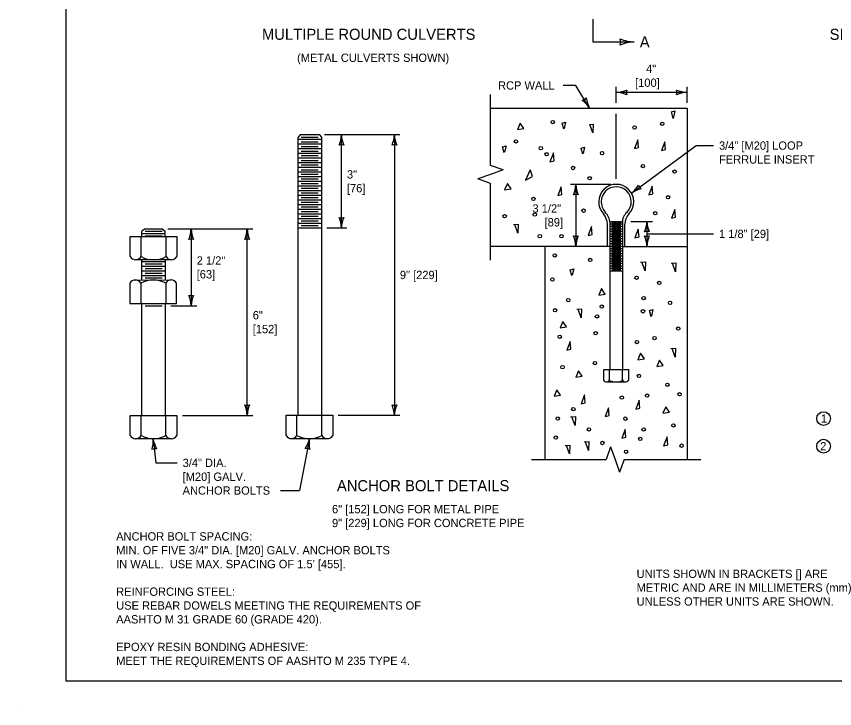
# Model space of a CAD drawing. Extents: x 49988.5 to 50021, y 49987.6 to 50011.4.
# Drawn here: x 49999.98 to 50005.9, y 49999.86 to 50004.87 of the extents above; entities that cross this region are included whole.
import ezdxf

# ---------------------------------------------------------------- set-up
doc = ezdxf.new("R2010")
doc.units = 0
for name, color, linetype in [('Level 1', 7, 'Continuous'), ('Level 2', 7, 'Continuous'), ('Level 3', 7, 'Continuous'), ('Level 5', 7, 'Continuous'), ('Level 6', 7, 'Continuous')]:
    doc.layers.add(name, color=color, linetype=linetype)

msp = doc.modelspace()

# ---------------------------------------------------------------- linework, layer by layer
at = {"layer": 'Level 1'}
for p, q in [((50003.4095, 50004.2058), (50004.8319, 50004.2058)), ((50004.8319, 50004.2058), (50004.8319, 50001.6643)), ((50002.0324, 50004.0145), (50002.0154, 50003.9975)), ((50002.0154, 50001.9847), (50002.0154, 50003.9975)), ((50002.0154, 50003.9808), (50002.1843, 50003.9808)), ((50002.0324, 50004.0145), (50002.1673, 50004.0145)), ((50002.0379, 50003.9976), (50002.1618, 50003.9976)), ((50002.0379, 50003.9638), (50002.1618, 50003.9638)), ((50002.1673, 50004.0145), (50002.1843, 50003.9975)), ((50002.1843, 50003.9975), (50002.1843, 50001.9847)), ((50002.0154, 50003.947), (50002.1843, 50003.947)), ((50002.0154, 50003.9133), (50002.1843, 50003.9133)), ((50002.0379, 50003.9301), (50002.1618, 50003.9301)), ((50002.0379, 50003.8963), (50002.1618, 50003.8963)), ((50002.0154, 50003.8795), (50002.1843, 50003.8795)), ((50002.0154, 50003.8458), (50002.1843, 50003.8458)), ((50002.0379, 50003.8626), (50002.1618, 50003.8626)), ((50002.0154, 50003.812), (50002.1843, 50003.812)), ((50002.0154, 50003.7783), (50002.1843, 50003.7783)), ((50002.0379, 50003.8288), (50002.1618, 50003.8288)), ((50002.0379, 50003.7951), (50002.1618, 50003.7951)), ((50002.0154, 50003.7445), (50002.1843, 50003.7445)), ((50002.0379, 50003.7613), (50002.1618, 50003.7613)), ((50002.0379, 50003.7276), (50002.1618, 50003.7276)), ((50002.0154, 50003.7108), (50002.1843, 50003.7108)), ((50002.0154, 50003.677), (50002.1843, 50003.677)), ((50002.0379, 50003.6938), (50002.1618, 50003.6938)), ((50002.0379, 50003.6601), (50002.1618, 50003.6601)), ((50002.0154, 50003.6433), (50002.1843, 50003.6433)), ((50002.0154, 50003.6095), (50002.1843, 50003.6095)), ((50002.0379, 50003.6263), (50002.1618, 50003.6263)), ((50002.0154, 50003.5758), (50002.1843, 50003.5758)), ((50002.0154, 50003.542), (50002.1843, 50003.542)), ((50002.0379, 50003.5926), (50002.1618, 50003.5926)), ((50002.0379, 50003.5588), (50002.1618, 50003.5588)), ((50002.0154, 50003.5083), (50002.1843, 50003.5083)), ((50002.0379, 50003.5251), (50002.1618, 50003.5251)), ((50002.0379, 50003.4913), (50002.1618, 50003.4913)), ((50002.0154, 50003.4745), (50002.1843, 50003.4745)), ((50002.0154, 50003.4408), (50002.1843, 50003.4408)), ((50002.0379, 50003.4576), (50002.1618, 50003.4576)), ((50002.0379, 50003.4238), (50002.1618, 50003.4238)), ((50002.0154, 50003.407), (50002.1843, 50003.407)), ((50002.0154, 50003.3733), (50002.1843, 50003.3733)), ((50002.0379, 50003.3901), (50002.1618, 50003.3901)), ((50004.2563, 50003.2059), (50004.2563, 50003.3676)), ((50004.2829, 50003.3871), (50004.2739, 50003.3781)), ((50004.2739, 50002.3146), (50004.2739, 50003.3781)), ((50004.2739, 50003.3693), (50004.3631, 50003.3693)), ((50004.2829, 50003.3871), (50004.3541, 50003.3871)), ((50004.2858, 50003.3781), (50004.3512, 50003.3781)), ((50004.3541, 50003.3871), (50004.3631, 50003.3781)), ((50004.3631, 50003.3781), (50004.3631, 50002.3146)), ((50004.3807, 50003.2059), (50004.3807, 50003.3676)), ((50000.9083, 50003.3327), (50000.8858, 50003.3159)), ((50000.8858, 50003.2782), (50000.8858, 50003.3159)), ((50000.9083, 50003.3327), (50001.032, 50003.3327)), ((50000.9083, 50003.3159), (50001.032, 50003.3159)), ((50001.032, 50003.3327), (50001.0545, 50003.3159)), ((50001.0545, 50003.2782), (50001.0545, 50003.3159)), ((50002.0154, 50003.3395), (50002.1843, 50003.3395)), ((50002.0379, 50003.3563), (50002.1618, 50003.3563)), ((50004.2739, 50003.3514), (50004.3631, 50003.3514)), ((50004.2739, 50003.3336), (50004.3631, 50003.3336)), ((50004.2739, 50003.3157), (50004.3631, 50003.3157)), ((50004.2858, 50003.3602), (50004.3512, 50003.3602)), ((50004.2858, 50003.3425), (50004.3512, 50003.3425)), ((50004.2858, 50003.3246), (50004.3512, 50003.3246)), ((50004.2858, 50003.3068), (50004.3512, 50003.3068)), ((50000.8012, 50003.132), (50000.8012, 50003.2782)), ((50000.8012, 50003.2782), (50001.1387, 50003.2782)), ((50000.8799, 50003.132), (50000.8799, 50003.2782)), ((50000.8858, 50003.2989), (50001.0545, 50003.2989)), ((50000.9083, 50003.2821), (50001.032, 50003.2821)), ((50001.0599, 50003.132), (50001.0599, 50003.2782)), ((50001.1387, 50003.2782), (50001.1387, 50003.132)), ((50004.2739, 50003.2979), (50004.3631, 50003.2979)), ((50004.2739, 50003.2801), (50004.3631, 50003.2801)), ((50004.2739, 50003.2623), (50004.3631, 50003.2623)), ((50004.2858, 50003.289), (50004.3512, 50003.289)), ((50004.2858, 50003.2712), (50004.3512, 50003.2712)), ((50004.2858, 50003.2533), (50004.3512, 50003.2533)), ((50004.2739, 50003.2058), (50003.4095, 50003.2058)), ((50003.8052, 50001.6643), (50003.8052, 50003.2058)), ((50004.2739, 50003.2445), (50004.3631, 50003.2445)), ((50004.2739, 50003.2267), (50004.3631, 50003.2267)), ((50004.2739, 50003.2088), (50004.3631, 50003.2088)), ((50004.2739, 50003.191), (50004.3631, 50003.191)), ((50004.2858, 50003.2355), (50004.3512, 50003.2355)), ((50004.2858, 50003.2176), (50004.3512, 50003.2176)), ((50004.2858, 50003.1999), (50004.3512, 50003.1999)), ((50004.3631, 50003.2058), (50004.8319, 50003.2058)), ((50004.2739, 50003.1731), (50004.3631, 50003.1731)), ((50004.2739, 50003.1553), (50004.3631, 50003.1553)), ((50004.2739, 50003.1375), (50004.3631, 50003.1375)), ((50004.2858, 50003.182), (50004.3512, 50003.182)), ((50004.2858, 50003.1642), (50004.3512, 50003.1642)), ((50004.2858, 50003.1464), (50004.3512, 50003.1464)), ((50004.2858, 50003.1286), (50004.3512, 50003.1286)), ((50001.0993, 50003.1092), (50000.8405, 50003.1095)), ((50000.8858, 50002.9632), (50000.8858, 50003.1095)), ((50000.8858, 50003.0964), (50001.0545, 50003.0964)), ((50000.9083, 50003.0796), (50001.032, 50003.0796)), ((50001.0545, 50003.1092), (50001.0545, 50002.9635)), ((50004.2739, 50003.1197), (50004.3631, 50003.1197)), ((50004.2739, 50003.1019), (50004.3631, 50003.1019)), ((50004.2739, 50003.0841), (50004.3631, 50003.0841)), ((50004.2858, 50003.1107), (50004.3512, 50003.1107)), ((50004.2858, 50003.0929), (50004.3512, 50003.0929)), ((50004.2858, 50003.075), (50004.3512, 50003.075)), ((50000.8858, 50003.0627), (50001.0545, 50003.0627)), ((50000.8858, 50003.0289), (50001.0545, 50003.0289)), ((50000.9083, 50003.0459), (50001.032, 50003.0459)), ((50000.9083, 50003.0121), (50001.032, 50003.0121)), ((50004.2739, 50003.0662), (50004.3631, 50003.0662)), ((50004.2739, 50003.0484), (50004.3631, 50003.0484)), ((50004.2739, 50003.0305), (50004.3631, 50003.0305)), ((50004.2858, 50003.0573), (50004.3512, 50003.0573)), ((50004.2858, 50003.0394), (50004.3512, 50003.0394)), ((50000.838, 50002.9631), (50001.0969, 50002.9635)), ((50000.8858, 50002.9952), (50001.0545, 50002.9952)), ((50000.9083, 50002.9784), (50001.032, 50002.9784)), ((50000.7986, 50002.9406), (50000.7986, 50002.7943)), ((50000.8774, 50002.9406), (50000.8774, 50002.7943)), ((50001.0575, 50002.9406), (50001.0575, 50002.7943)), ((50001.1363, 50002.7943), (50001.1363, 50002.9406)), ((50000.7986, 50002.7943), (50001.1363, 50002.7943)), ((50000.8858, 50001.984), (50000.8858, 50002.7943)), ((50000.8858, 50002.7927), (50001.0545, 50002.7927)), ((50000.9083, 50002.7759), (50001.032, 50002.7759)), ((50001.0545, 50002.7943), (50001.0545, 50001.984)), ((50004.2281, 50002.2373), (50004.2281, 50002.3146)), ((50004.2281, 50002.3146), (50004.4064, 50002.3146)), ((50004.2698, 50002.2373), (50004.2698, 50002.3146)), ((50004.3648, 50002.2373), (50004.3648, 50002.3146)), ((50004.4064, 50002.3146), (50004.4064, 50002.2373)), ((50004.249, 50002.2255), (50004.3856, 50002.2253)), ((50000.8004, 50001.8377), (50000.8004, 50001.984)), ((50000.8004, 50001.984), (50001.1381, 50001.984)), ((50000.8792, 50001.8377), (50000.8792, 50001.984)), ((50001.0593, 50001.8377), (50001.0593, 50001.984)), ((50001.1381, 50001.984), (50001.1381, 50001.8377)), ((50001.9286, 50001.8384), (50001.9286, 50001.9847)), ((50001.9286, 50001.9847), (50002.2663, 50001.9847)), ((50002.0074, 50001.8384), (50002.0074, 50001.9847)), ((50002.1875, 50001.8384), (50002.1875, 50001.9847)), ((50002.2663, 50001.9847), (50002.2663, 50001.8384)), ((50001.0987, 50001.8148), (50000.8398, 50001.8152)), ((50001.968, 50001.8159), (50002.2269, 50001.8155)), ((49999.9766, 49999.8624), (49999.9766, 49999.8624))]:
    msp.add_line(p, q, dxfattribs=at)
msp.add_lwpolyline([(50008.6146, 50011.2628), (50000.3356, 50011.2628), (50000.3356, 50000.0624), (50008.6146, 50000.0624)], close=True, dxfattribs=at)
for points in [[(50004.7314, 50004.1318), (50004.7183, 50004.1789), (50004.7428, 50004.1862), (50004.7314, 50004.1319)], [(50003.6238, 50004.0981), (50003.6042, 50004.0515), (50003.6507, 50004.0589), (50003.6238, 50004.0981)], [(50003.9397, 50004.054), (50003.9274, 50004.0981), (50003.9519, 50004.1054), (50003.9421, 50004.0589)], [(50004.1274, 50004.089), (50004.1526, 50004.0908), (50004.1502, 50004.0271), (50004.1278, 50004.089)], [(50004.4759, 50003.9781), (50004.4514, 50003.9144), (50004.4808, 50003.9218), (50004.4759, 50003.9781)], [(50004.6717, 50003.9634), (50004.6472, 50003.8997), (50004.6766, 50003.9071), (50004.6717, 50003.9634)], [(50003.5087, 50003.8826), (50003.4964, 50003.9267), (50003.5209, 50003.934), (50003.5111, 50003.8875)], [(50004.0768, 50003.8728), (50004.0645, 50003.9169), (50004.089, 50003.9242), (50004.0792, 50003.8777)], [(50003.8636, 50003.8826), (50003.8391, 50003.8189), (50003.8685, 50003.8263), (50003.8636, 50003.8826)], [(50003.6948, 50003.7602), (50003.663, 50003.6843), (50003.7119, 50003.7112), (50003.6972, 50003.7553)], [(50003.5308, 50003.6623), (50003.5112, 50003.6157), (50003.5577, 50003.6231), (50003.5308, 50003.6623)], [(50003.9204, 50003.6383), (50003.8959, 50003.5746), (50003.9253, 50003.582), (50003.9204, 50003.6383)], [(50004.5784, 50003.6423), (50004.5539, 50003.5786), (50004.5833, 50003.586), (50004.5784, 50003.6423)], [(50004.7434, 50003.4735), (50004.7189, 50003.4098), (50004.7483, 50003.4172), (50004.7434, 50003.4735)], [(50003.5747, 50003.3635), (50003.609, 50003.366), (50003.6066, 50003.3023), (50003.5845, 50003.3635)], [(50004.1394, 50003.3495), (50004.1149, 50003.2858), (50004.1443, 50003.2932), (50004.1394, 50003.3495)], [(50004.4787, 50003.3318), (50004.4542, 50003.2681), (50004.4836, 50003.2755), (50004.4787, 50003.3318)], [(50004.4954, 50003.0917), (50004.5297, 50003.0942), (50004.5273, 50003.0305), (50004.5052, 50003.0917)], [(50004.7158, 50003.0843), (50004.7501, 50003.0868), (50004.7477, 50003.0231), (50004.7256, 50003.0843)], [(50003.9985, 50002.9937), (50003.9862, 50003.0378), (50004.0107, 50003.0451), (50004.0009, 50002.9986)], [(50004.2115, 50002.9008), (50004.1919, 50002.8542), (50004.2384, 50002.8616), (50004.2115, 50002.9008)], [(50004.0326, 50002.7513), (50004.0669, 50002.7538), (50004.0645, 50002.6901), (50004.0424, 50002.7513)], [(50004.5715, 50002.6974), (50004.5592, 50002.7415), (50004.5837, 50002.7488), (50004.5739, 50002.7023)], [(50003.9323, 50002.6632), (50003.9127, 50002.6166), (50003.9592, 50002.624), (50003.9323, 50002.6632)], [(50003.9861, 50002.5187), (50003.9616, 50002.455), (50003.991, 50002.4624), (50003.9861, 50002.5187)], [(50004.4955, 50002.433), (50004.4759, 50002.3864), (50004.5224, 50002.3938), (50004.4955, 50002.433)], [(50004.7133, 50002.4673), (50004.7476, 50002.4698), (50004.7452, 50002.4061), (50004.7231, 50002.4673)], [(50004.6326, 50002.384), (50004.613, 50002.3374), (50004.6595, 50002.3448), (50004.6326, 50002.384)], [(50004.045, 50002.3057), (50004.0254, 50002.2591), (50004.0719, 50002.2665), (50004.045, 50002.3057)], [(50003.8882, 50002.1686), (50003.8686, 50002.122), (50003.9151, 50002.1294), (50003.8882, 50002.1686)], [(50004.0889, 50002.1318), (50004.0644, 50002.0681), (50004.0938, 50002.0755), (50004.0889, 50002.1318)], [(50004.4849, 50002.0929), (50004.4604, 50002.0292), (50004.4898, 50002.0366), (50004.4849, 50002.0929)], [(50004.2637, 50002.0382), (50004.2392, 50001.9745), (50004.2686, 50001.9819), (50004.2637, 50002.0382)], [(50004.6767, 50002.0461), (50004.6571, 50001.9995), (50004.7036, 50002.0069), (50004.6767, 50002.0461)], [(50003.9885, 50001.9727), (50004.0228, 50001.9752), (50004.0204, 50001.9115), (50003.9983, 50001.9727)], [(50004.3837, 50001.8826), (50004.3592, 50001.8189), (50004.3886, 50001.8263), (50004.3837, 50001.8826)], [(50004.6864, 50001.8281), (50004.6619, 50001.7644), (50004.6913, 50001.7718), (50004.6864, 50001.8281)], [(50003.9493, 50001.767), (50003.9836, 50001.7695), (50003.9812, 50001.7058), (50003.9591, 50001.767)], [(50004.0864, 50001.7915), (50004.1207, 50001.794), (50004.1183, 50001.7303), (50004.0962, 50001.7915)]]:
    msp.add_lwpolyline(points, dxfattribs=at)
for centre in [(50003.8589, 50004.1054), (50004.4514, 50004.0662), (50004.6522, 50004.0932), (50003.5931, 50003.966), (50003.7731, 50003.9169), (50003.8148, 50003.8728), (50004.216, 50003.8806), (50004.0063, 50003.7734), (50004.5117, 50003.7873), (50004.7415, 50003.7477), (50004.1265, 50003.6994), (50003.7193, 50003.5496), (50004.6944, 50003.5615), (50003.5111, 50003.4247), (50003.7297, 50003.436), (50004.0821, 50003.4648), (50004.6009, 50003.4457), (50003.7658, 50003.2802), (50003.9226, 50003.2795), (50003.8735, 50003.1407), (50004.1307, 50003.1088), (50003.8564, 50002.9668), (50004.4661, 50002.979), (50004.6302, 50002.9423), (50004.5175, 50002.8322), (50003.9715, 50002.8174), (50004.2139, 50002.7709), (50004.7085, 50002.7978), (50003.8759, 50002.744), (50004.1796, 50002.6999), (50004.5126, 50002.7366), (50004.7673, 50002.6118), (50003.9102, 50002.553), (50004.1698, 50002.5775), (50004.5958, 50002.5432), (50004.4685, 50002.5138), (50004.1649, 50002.362), (50003.9298, 50002.3326), (50004.4832, 50002.269), (50004.6889, 50002.2053), (50004.3592, 50002.1125), (50004.542, 50002.127), (50004.777, 50002.1368), (50004.0082, 50002.029), (50003.8955, 50001.9604), (50004.3853, 50001.9599), (50004.1208, 50001.8821), (50004.5175, 50001.8821), (50004.733, 50001.9115), (50003.8808, 50001.8233), (50004.493, 50001.8135), (50004.2188, 50001.7841), (50004.7917, 50001.7646), (50004.3902, 50001.7205)]:
    msp.add_circle(centre, 0.0122, dxfattribs=at)
for centre, radius, start, end in [((50004.3185, 50003.5284), 0.1268, 316.22989, 223.74501), ((50004.3185, 50003.5284), 0.1092, 316.22989, 223.74501), ((50004.1208, 50003.3557), 0.136, 5.0488, 38.70521), ((50004.1617, 50003.372), 0.1124, 3.14279, 46.05746), ((50004.4556, 50003.381), 0.0925, 129.00174, 181.76483), ((50004.5049, 50003.3602), 0.1244, 139.65882, 176.55864), ((50000.8405, 50003.1552), 0.0457, 210.47161, 329.52839), ((50000.9699, 50003.2992), 0.1899, 241.7026, 298.2974), ((50001.0993, 50003.1545), 0.0454, 209.72849, 330.27151), ((50000.838, 50002.9174), 0.0457, 30.53773, 149.46227), ((50000.9674, 50002.7733), 0.19, 61.71077, 118.28923), ((50001.0969, 50002.9182), 0.0454, 29.69997, 150.30003), ((50004.249, 50002.2499), 0.0243, 210.97951, 329.02049), ((50004.3173, 50002.3262), 0.1008, 241.88299, 298.11701), ((50004.3856, 50002.2494), 0.024, 210.08662, 329.91338), ((50000.8398, 50001.861), 0.0457, 210.53773, 329.46227), ((50000.9693, 50002.0051), 0.19, 241.71077, 298.28923), ((50001.0987, 50001.8602), 0.0454, 209.69997, 330.30003), ((50001.968, 50001.8617), 0.0457, 210.53773, 329.46227), ((50002.0975, 50002.0058), 0.19, 241.71077, 298.28923), ((50002.2269, 50001.8609), 0.0454, 209.69997, 330.30003)]:
    msp.add_arc(centre, radius, start, end, dxfattribs=at)
at = {"layer": 'Level 2'}
for centre in [(50005.82, 50001.9606), (50005.82, 50001.7606)]:
    msp.add_circle(centre, 0.05, dxfattribs=at)
at = {"layer": 'Level 3'}
for p, q in [((50004.0274, 50004.3706), (50003.9358, 50004.3706)), ((50004.1263, 50004.2058), (50004.0274, 50004.3706)), ((50004.3185, 50004.2458), (50004.3185, 50004.3605)), ((50004.8319, 50004.3205), (50004.3185, 50004.3205)), ((50004.8319, 50004.2458), (50004.8319, 50004.3605)), ((50002.2073, 50004.0145), (50002.7529, 50004.0145)), ((50002.3295, 50003.3395), (50002.3295, 50004.0145)), ((50002.7129, 50004.0145), (50002.7129, 50001.9847)), ((50004.4287, 50003.591), (50004.8969, 50003.9356)), ((50004.8969, 50003.9356), (50005.0226, 50003.9356)), ((50004.2785, 50003.6551), (50003.9866, 50003.6551)), ((50004.0266, 50003.6551), (50004.0266, 50003.2058)), ((50004.4234, 50003.3871), (50004.581, 50003.3871)), ((50004.541, 50003.3871), (50004.541, 50003.2058)), ((50001.072, 50003.3327), (50001.6876, 50003.3327)), ((50001.2421, 50003.3327), (50001.2421, 50002.7759)), ((50001.6476, 50001.984), (50001.6476, 50003.3327)), ((50002.2243, 50003.3395), (50002.3695, 50003.3395)), ((50004.541, 50003.2965), (50005.0226, 50003.2965)), ((50001.0945, 50002.7759), (50001.2821, 50002.7759)), ((50001.1781, 50001.984), (50001.6876, 50001.984)), ((50002.3063, 50001.9847), (50002.7529, 50001.9847)), ((50000.9661, 50001.815), (50000.9869, 50001.6402)), ((50002.0978, 50001.8157), (50002.0267, 50001.4402)), ((50000.9869, 50001.6402), (50001.1401, 50001.6402)), ((50001.8885, 50001.4402), (50002.0267, 50001.4402))]:
    msp.add_line(p, q, dxfattribs=at)
for centre, radius, start, end in [((50004.307, 50004.5532), 0.233, 272.82731, 292.07716), ((50004.3093, 50004.0984), 0.2223, 67.45601, 87.63952), ((50004.4467, 50004.3205), 0.0548, 162.13882, 197.86118), ((50004.8411, 50004.5427), 0.2223, 247.45601, 267.63952), ((50004.7037, 50004.3205), 0.0548, 342.13882, 17.86118), ((50004.8434, 50004.0878), 0.233, 92.82731, 112.07716), ((50004.0611, 50004.3163), 0.0548, 282.67255, 318.39491), ((50003.9317, 50004.0777), 0.233, 33.36104, 52.61089), ((50004.3223, 50004.3108), 0.2223, 187.98974, 208.17325), ((50002.1074, 50004.0237), 0.2223, 337.45601, 357.63952), ((50002.5622, 50004.026), 0.233, 182.82731, 202.07716), ((50002.4908, 50004.0237), 0.2223, 337.45601, 357.63952), ((50002.9456, 50004.026), 0.233, 182.82731, 202.07716), ((50002.3295, 50003.8863), 0.0548, 72.13882, 107.86118), ((50002.7129, 50003.8863), 0.0548, 72.13882, 107.86118), ((50003.8045, 50003.6643), 0.2223, 337.45601, 357.63952), ((50004.2593, 50003.6666), 0.233, 182.82731, 202.07716), ((50004.2815, 50003.7716), 0.233, 309.1887, 328.43855), ((50004.5531, 50003.4067), 0.2223, 103.8174, 124.00091), ((50004.532, 50003.667), 0.0548, 198.50021, 234.22257), ((50004.0266, 50003.5269), 0.0548, 72.13882, 107.86118), ((50002.3295, 50003.4677), 0.0548, 252.13882, 287.86118), ((50002.0968, 50003.328), 0.233, 2.82731, 22.07716), ((50002.5516, 50003.3304), 0.2223, 157.45601, 177.63952), ((50004.3189, 50003.3963), 0.2223, 337.45601, 357.63952), ((50004.7737, 50003.3986), 0.233, 182.82731, 202.07716), ((50001.02, 50003.3419), 0.2223, 337.45601, 357.63952), ((50001.4748, 50003.3442), 0.233, 182.82731, 202.07716), ((50001.4254, 50003.3419), 0.2223, 337.45601, 357.63952), ((50001.8803, 50003.3442), 0.233, 182.82731, 202.07716), ((50004.541, 50003.2589), 0.0548, 72.13882, 107.86118), ((50001.2421, 50003.2045), 0.0548, 72.13882, 107.86118), ((50001.6476, 50003.2045), 0.0548, 72.13882, 107.86118), ((50004.0266, 50003.334), 0.0548, 252.13882, 287.86118), ((50003.7939, 50003.1943), 0.233, 2.82731, 22.07716), ((50004.2487, 50003.1967), 0.2223, 157.45601, 177.63952), ((50004.541, 50003.334), 0.0548, 252.13882, 287.86118), ((50004.3083, 50003.1943), 0.233, 2.82731, 22.07716), ((50004.7632, 50003.1967), 0.2223, 157.45601, 177.63952), ((50001.2421, 50002.9041), 0.0548, 252.13882, 287.86118), ((50001.0094, 50002.7644), 0.233, 2.82731, 22.07716), ((50001.4642, 50002.7668), 0.2223, 157.45601, 177.63952), ((50002.7129, 50002.1129), 0.0548, 252.13882, 287.86118), ((50002.4802, 50001.9732), 0.233, 2.82731, 22.07716), ((50002.935, 50001.9756), 0.2223, 157.45601, 177.63952), ((50001.6476, 50002.1122), 0.0548, 252.13882, 287.86118), ((50001.4148, 50001.9725), 0.233, 2.82731, 22.07716), ((50001.8697, 50001.9749), 0.2223, 157.45601, 177.63952), ((50000.7445, 50001.798), 0.2223, 344.22455, 4.40806), ((50001.1959, 50001.8539), 0.233, 189.59585, 208.8457), ((50001.8813, 50001.8661), 0.2223, 326.7241, 346.90761), ((50002.3286, 50001.7837), 0.233, 172.0954, 191.34525), ((50000.9812, 50001.6877), 0.0548, 78.90736, 114.62972), ((50002.074, 50001.6898), 0.0548, 61.40691, 97.12927)]:
    msp.add_arc(centre, radius, start, end, dxfattribs=at)
at = {"layer": 'Level 5'}
msp.add_line((50004.3185, 50003.6951), (50004.3185, 50004.1658), dxfattribs=at)
at = {"layer": 'Level 6'}
for p, q in [((50004.1493, 50004.8507), (50004.1493, 50004.6852)), ((50004.1493, 50004.6852), (50004.4493, 50004.6852)), ((50003.4095, 50003.7915), (50003.4095, 50004.3058)), ((50003.5009, 50003.7591), (50003.4095, 50003.7915)), ((50003.4095, 50003.7267), (50003.3181, 50003.6943)), ((50003.5009, 50003.7591), (50003.4095, 50003.7267)), ((50003.4095, 50003.6619), (50003.3181, 50003.6943)), ((50003.4095, 50003.1058), (50003.4095, 50003.6619)), ((50004.2784, 50001.7557), (50004.246, 50001.6643)), ((50004.2784, 50001.7557), (50004.3108, 50001.6643)), ((50003.7052, 50001.6643), (50004.246, 50001.6643)), ((50004.3108, 50001.6643), (50004.3432, 50001.5729)), ((50004.3756, 50001.6643), (50004.3432, 50001.5729)), ((50004.3756, 50001.6643), (50004.9319, 50001.6643))]:
    msp.add_line(p, q, dxfattribs=at)
for centre, radius, start, end in [((50004.4615, 50004.9814), 0.2964, 247.45601, 267.63952), ((50004.2783, 50004.6852), 0.073, 342.13882, 17.86118), ((50004.4646, 50004.375), 0.3107, 92.82731, 112.07716)]:
    msp.add_arc(centre, radius, start, end, dxfattribs=at)

# ---------------------------------------------------------------- texts
at = {"layer": 'Level 2'}
for s, height, p in [('MULTIPLE ROUND CULVERTS', 0.08, (50001.7544, 50004.7008)), ('SINGLE ROUND CULVERT', 0.08, (50005.8635, 50004.7003)), ('A', 0.08, (50004.4893, 50004.6452)), ('(METAL CULVERTS SHOWN)', 0.06, (50002.0086, 50004.5408)), ('4"', 0.06, (50004.535, 50004.4605)), ('RCP WALL', 0.06, (50003.4632, 50004.3407)), ('[100]', 0.06, (50004.4552, 50004.3605)), ('3/4" [M20] LOOP', 0.06, (50005.0626, 50003.9056)), ('FERRULE INSERT', 0.06, (50005.0626, 50003.8056)), ('3"', 0.06, (50002.3695, 50003.6971)), ('[76]', 0.06, (50002.3695, 50003.5971)), ('3 1/2"', 0.06, (50003.7125, 50003.4505)), ('[89]', 0.06, (50003.8, 50003.3505)), ('1 1/8" [29]', 0.06, (50005.0626, 50003.2665)), ('2 1/2"', 0.06, (50001.2821, 50003.0743)), ('[63]', 0.06, (50001.2821, 50002.9743)), ('9" [229]', 0.06, (50002.7529, 50002.9696)), ('6"', 0.06, (50001.6876, 50002.6784)), ('[152]', 0.06, (50001.6876, 50002.5784)), ('1', 0.06, (50005.8002, 50001.9306)), ('2', 0.06, (50005.7948, 50001.7306)), ('3/4" DIA.', 0.06, (50001.18, 50001.6102)), ('[M20] GALV. ', 0.06, (50001.18, 50001.5102)), ('ANCHOR BOLTS', 0.06, (50001.18, 50001.4102)), ('ANCHOR BOLT DETAILS', 0.08, (50002.2969, 50001.4354)), ('6" [152] LONG FOR METAL PIPE', 0.06, (50002.2613, 50001.2754)), ('9" [229] LONG FOR CONCRETE PIPE', 0.06, (50002.2613, 50001.1754)), ('ANCHOR BOLT SPACING:', 0.06, (50000.6991, 50001.0784)), ('MIN. OF FIVE 3/4" DIA. [M20] GALV. ANCHOR BOLTS', 0.06, (50000.6991, 50000.9784)), ("IN WALL.  USE MAX. SPACING OF 1.5' [455].", 0.06, (50000.6991, 50000.8784)), ('UNITS SHOWN IN BRACKETS [] ARE', 0.06, (50004.4665, 50000.8076)), ('METRIC AND ARE IN MILLIMETERS (mm) ', 0.06, (50004.4665, 50000.7076)), ('REINFORCING STEEL:', 0.06, (50000.6991, 50000.6784)), ('USE REBAR DOWELS MEETING THE REQUIREMENTS OF', 0.06, (50000.6991, 50000.5784)), ('UNLESS OTHER UNITS ARE SHOWN.', 0.06, (50004.4665, 50000.6076)), ('AASHTO M 31 GRADE 60 (GRADE 420).', 0.06, (50000.6991, 50000.4784)), ('EPOXY RESIN BONDING ADHESIVE:', 0.06, (50000.6991, 50000.2784)), ('MEET THE REQUIREMENTS OF AASHTO M 235 TYPE 4.', 0.06, (50000.6991, 50000.1784))]:
    msp.add_text(s, height=height, dxfattribs=at).set_placement(p)

doc.saveas('drawing.dxf')
